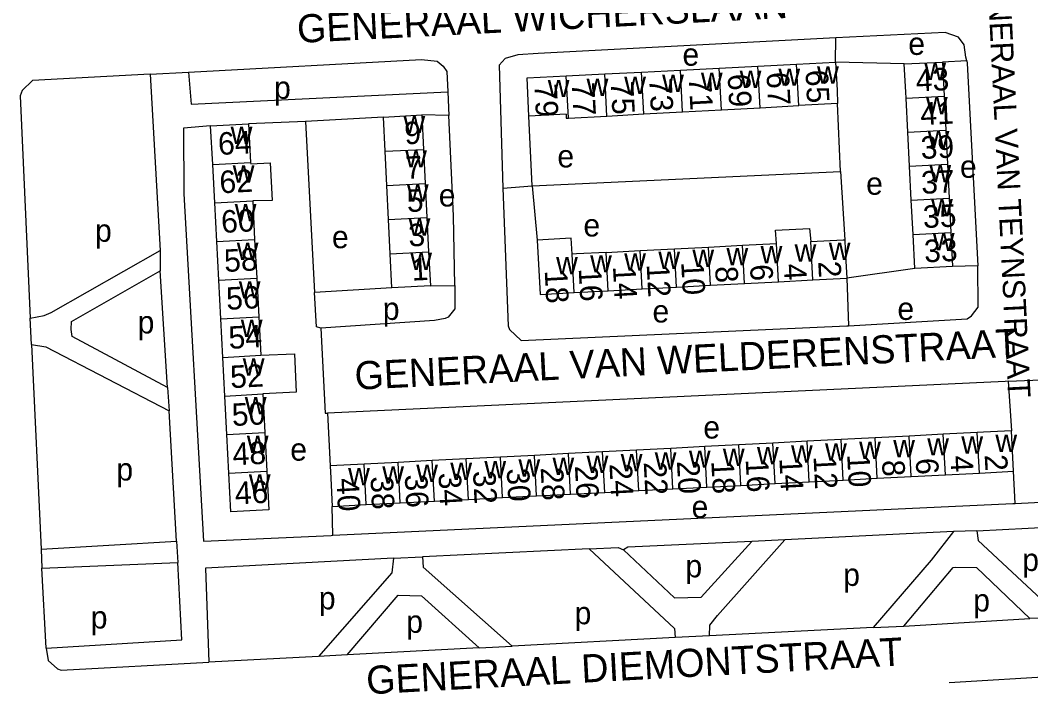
# Model space of a CAD drawing. Extents: x 159294 to 161936, y 384538 to 386517.
# Drawn here: x 161619.2 to 161798.8, y 386008.7 to 386126.3 of the extents above; entities that cross this region are included whole.
import ezdxf

# ---------------------------------------------------------------- set-up
doc = ezdxf.new("R2010")
doc.units = 0
for name, color, linetype in [('BLT_Basislijn', 7, 'Continuous'), ('BLT_Bebouwing', 7, 'Continuous'), ('BLT_Centroide', 7, 'Continuous'), ('BLT_Huisnummer', 7, 'Continuous'), ('BLT_Huisnummer_ tussenligend', 7, 'Continuous'), ('BLT_Onderverdeling_panden', 7, 'Continuous'), ('BLT_Straatnaam', 7, 'Continuous'), ('BLT_Straatnaam_verkleind', 7, 'Continuous')]:
    doc.layers.add(name, color=color, linetype=linetype)

msp = doc.modelspace()

# ---------------------------------------------------------------- linework, layer by layer
at = {"layer": 'BLT_Basislijn'}
for p, q in [((161764.11, 386118.85), (161764.14, 386123.15)), ((161776.3, 386118.52), (161764.11, 386118.85)), ((161787.4, 386119.09), (161783.1, 386118.86)), ((161642.28, 386116.7), (161649.06, 386117.08)), ((161642.28, 386116.7), (161644.03, 386085.36)), ((161695.18, 386113.54), (161695.35, 386109.36)), ((161764.98, 386099.42), (161764.46, 386111.5)), ((161695.35, 386109.36), (161690.55, 386109.45)), ((161710.18, 386096.88), (161709.6, 386109.23)), ((161669.86, 386108.29), (161659.77, 386107.88)), ((161683.73, 386109.07), (161669.86, 386108.29)), ((161669.86, 386108.29), (161671.49, 386077.92)), ((161710.18, 386096.88), (161764.98, 386099.42)), ((161764.98, 386099.42), (161765.73, 386087.27)), ((161704.95, 386096.46), (161710.18, 386096.88)), ((161710.18, 386096.88), (161711.07, 386087.22)), ((161644.03, 386085.36), (161644.06, 386081.72)), ((161778.19, 386082.17), (161766.08, 386080.46)), ((161789.36, 386082.65), (161784.88, 386082.49)), ((161645.37, 386061.03), (161644.06, 386081.72)), ((161766.08, 386080.46), (161766.42, 386071.96)), ((161685.24, 386078.71), (161671.49, 386077.92)), ((161692.07, 386079.05), (161696.45, 386079.14)), ((161621.16, 386068.63), (161620.93, 386073.33)), ((161621.16, 386068.63), (161622.88, 386032.29)), ((161645.37, 386061.03), (161645.65, 386056.83)), ((161794.75, 386062.11), (161795.35, 386053.32)), ((161646.95, 386033.66), (161645.65, 386056.83)), ((161673.77, 386056.44), (161674.24, 386047.06)), ((161796.04, 386040.41), (161795.72, 386046.11)), ((161796.04, 386040.41), (161806.44, 386040.89)), ((161674.74, 386034.73), (161674.62, 386039.86)), ((161789.19, 386035.5), (161785.08, 386035.4)), ((161789.19, 386035.5), (161806.72, 386036.45)), ((161755.06, 386033.94), (161749.19, 386033.62)), ((161785.08, 386035.4), (161755.06, 386033.94)), ((161622.88, 386032.29), (161646.95, 386033.66)), ((161622.88, 386032.29), (161623.03, 386028.88)), ((161646.95, 386033.66), (161647.17, 386029.87)), ((161720.3, 386032.31), (161690.68, 386030.9)), ((161685.51, 386030.64), (161690.68, 386030.9)), ((161623.03, 386028.88), (161647.17, 386029.87)), ((161623.81, 386014.67), (161623.03, 386028.88)), ((161776.24, 386018.59), (161798.6, 386019.96)), ((161804.16, 386020.13), (161798.6, 386019.96)), ((161770.75, 386018.32), (161741.68, 386016.84)), ((161770.75, 386018.32), (161776.24, 386018.59)), ((161735.56, 386016.56), (161706.6, 386015)), ((161741.68, 386016.84), (161735.56, 386016.56)), ((161700.77, 386014.71), (161677.29, 386013.48)), ((161700.77, 386014.71), (161706.6, 386015)), ((161672.2, 386013.2), (161652.67, 386012.16)), ((161677.29, 386013.48), (161672.2, 386013.2))]:
    msp.add_line(p, q, dxfattribs=at)
for points in [[(161787.4, 386119.09), (161787.25, 386119.71), (161786.98, 386121.9), (161785.95, 386123.26), (161783.56, 386124.1), (161764.14, 386123.15)], [(161764.14, 386123.15), (161711.23, 386120.4), (161707.6, 386120.17), (161705.35, 386119.48), (161704.28, 386118.32), (161704.95, 386096.46)], [(161649.06, 386117.08), (161690.49, 386119.3), (161693.26, 386119.01), (161694.37, 386118.15), (161695.01, 386117.19), (161695.18, 386113.54)], [(161787.4, 386119.09), (161787.5, 386118.69), (161789.36, 386082.65)], [(161642.28, 386116.7), (161621.35, 386115.6)], [(161649.06, 386117.08), (161649.53, 386111.36), (161695.18, 386113.54)], [(161621.35, 386115.6), (161619.49, 386113.8), (161619.17, 386112.83), (161620.93, 386073.33)], [(161696.45, 386079.14), (161696.19, 386091.54), (161695.35, 386109.36)], [(161653.02, 386107.53), (161648.18, 386107.13), (161648.27, 386095.46), (161651.77, 386033.68), (161674.46, 386034.72), (161674.74, 386034.73)], [(161704.95, 386096.46), (161705.93, 386071.97), (161706.16, 386071.33), (161708.21, 386069.34), (161766.11, 386071.94), (161766.42, 386071.96)], [(161620.93, 386073.33), (161623.44, 386073.79), (161624.67, 386074.34), (161644.03, 386085.36)], [(161766.42, 386071.96), (161787.46, 386073.24), (161788.26, 386073.72), (161789.44, 386075.31), (161789.36, 386082.65)], [(161645.37, 386061.03), (161628.39, 386070.06), (161628.23, 386071.31), (161628.29, 386072.76), (161644.06, 386081.72)], [(161696.45, 386079.14), (161696.44, 386074.99), (161695.25, 386073.52), (161694.7, 386073.3), (161692.82, 386072.94), (161672.6, 386071.56)], [(161672.6, 386071.56), (161671.86, 386071.81), (161671.49, 386077.92)], [(161672.6, 386071.56), (161673.37, 386056.42), (161673.77, 386056.44)], [(161621.16, 386068.63), (161623.74, 386068.21), (161645.65, 386056.83)], [(161794.75, 386062.11), (161804.96, 386062.57), (161806.44, 386040.89)], [(161794.75, 386062.11), (161794.25, 386062.09), (161673.77, 386056.44)], [(161674.74, 386034.73), (161795.62, 386040.39), (161796.04, 386040.41)], [(161789.19, 386035.5), (161789.45, 386033.78), (161804.16, 386020.13)], [(161741.68, 386016.84), (161741.77, 386018.78), (161743.11, 386020.5), (161755.06, 386033.94)], [(161785.08, 386035.4), (161781.11, 386030.31), (161770.75, 386018.32)], [(161720.3, 386032.31), (161725.47, 386032.54), (161726.4, 386032.13)], [(161720.3, 386032.31), (161735.46, 386018.15), (161735.56, 386016.56)], [(161726.4, 386032.13), (161735.47, 386023.61), (161740.23, 386023.75), (161749.19, 386033.62)], [(161749.19, 386033.62), (161727.19, 386032.62), (161726.4, 386032.13)], [(161685.51, 386030.64), (161652.11, 386028.88), (161652.67, 386012.16)], [(161685.51, 386030.64), (161685.23, 386028.08), (161672.2, 386013.2)], [(161690.68, 386030.9), (161690.77, 386029.04), (161706.6, 386015)], [(161623.81, 386014.67), (161647.88, 386016.13), (161647.17, 386029.87)], [(161776.24, 386018.59), (161784.99, 386028.98), (161785.39, 386029.06), (161789.12, 386028.98), (161798.6, 386019.96)], [(161677.29, 386013.48), (161686.35, 386024.1), (161690.49, 386023.96), (161700.77, 386014.71)], [(161623.81, 386014.67), (161624.15, 386012.48), (161625.82, 386010.98), (161626.44, 386010.74), (161652.67, 386012.16)], [(161784.28, 386008.54), (161803.88, 386009.76), (161805.74, 386009.74), (161807.33, 386008.66), (161808.62, 385995.18), (161809.8, 385968.48)]]:
    msp.add_lwpolyline(points, dxfattribs=at)
at = {"layer": 'BLT_Bebouwing'}
for p, q in [((161743.4, 386117.79), (161750.29, 386118.14)), ((161750.29, 386118.14), (161757.18, 386118.5)), ((161757.18, 386118.5), (161764.11, 386118.85)), ((161776.3, 386118.52), (161783.1, 386118.86)), ((161783.1, 386118.86), (161783.4, 386112.81)), ((161716.24, 386116.39), (161723.06, 386116.74)), ((161723.06, 386116.74), (161729.62, 386117.08)), ((161729.62, 386117.08), (161736.51, 386117.43)), ((161736.51, 386117.43), (161743.4, 386117.79)), ((161783.4, 386112.81), (161783.69, 386106.75)), ((161750.69, 386110.75), (161757.58, 386111.12)), ((161764.46, 386111.5), (161757.58, 386111.12)), ((161776.93, 386106.4), (161776.62, 386112.46)), ((161683.73, 386109.07), (161690.55, 386109.45)), ((161690.55, 386109.45), (161690.85, 386103.34)), ((161716.2, 386109.58), (161709.6, 386109.23)), ((161723.44, 386109.27), (161730.02, 386109.63)), ((161730.02, 386109.63), (161736.91, 386110)), ((161736.91, 386110), (161743.8, 386110.38)), ((161743.8, 386110.38), (161750.69, 386110.75)), ((161653.02, 386107.53), (161659.77, 386107.88)), ((161653.38, 386100.67), (161653.02, 386107.53)), ((161659.77, 386107.88), (161660.13, 386101.02)), ((161684.03, 386103), (161683.73, 386109.07)), ((161777.24, 386100.34), (161776.93, 386106.4)), ((161783.69, 386106.75), (161783.99, 386100.7)), ((161684.34, 386096.93), (161684.03, 386103)), ((161690.85, 386103.34), (161691.16, 386097.27)), ((161653.74, 386093.81), (161653.38, 386100.67)), ((161777.56, 386094.29), (161777.24, 386100.34)), ((161783.99, 386100.7), (161784.28, 386094.64)), ((161684.64, 386090.86), (161684.34, 386096.93)), ((161691.16, 386097.27), (161691.46, 386091.2)), ((161654.1, 386086.94), (161653.74, 386093.81)), ((161660.49, 386094.16), (161660.84, 386087.3)), ((161777.87, 386088.23), (161777.56, 386094.29)), ((161784.28, 386094.64), (161784.58, 386088.58)), ((161691.46, 386091.2), (161691.76, 386085.12)), ((161684.94, 386084.79), (161684.64, 386090.86)), ((161778.19, 386082.17), (161777.87, 386088.23)), ((161784.58, 386088.58), (161784.88, 386082.49)), ((161654.46, 386080.08), (161654.1, 386086.94)), ((161660.84, 386087.3), (161661.2, 386080.43)), ((161741.49, 386085.98), (161747.55, 386086.3)), ((161747.55, 386086.3), (161753.61, 386086.62)), ((161759.67, 386086.95), (161765.45, 386087.25)), ((161765.45, 386087.25), (161765.73, 386087.27)), ((161685.24, 386078.71), (161684.94, 386084.79)), ((161691.76, 386085.12), (161692.07, 386079.05)), ((161723.32, 386085.02), (161729.38, 386085.34)), ((161729.38, 386085.34), (161735.44, 386085.66)), ((161784.88, 386082.49), (161778.19, 386082.17)), ((161661.2, 386080.43), (161661.56, 386073.57)), ((161760.03, 386080.14), (161766.08, 386080.46)), ((161654.82, 386073.22), (161654.46, 386080.08)), ((161692.07, 386079.05), (161685.24, 386078.71)), ((161729.74, 386078.53), (161735.8, 386078.85)), ((161735.8, 386078.85), (161741.86, 386079.17)), ((161741.86, 386079.17), (161747.91, 386079.49)), ((161747.91, 386079.49), (161753.97, 386079.82)), ((161753.97, 386079.82), (161760.03, 386080.14)), ((161717.63, 386077.88), (161723.68, 386078.2)), ((161723.68, 386078.2), (161729.74, 386078.53)), ((161655.18, 386066.36), (161654.82, 386073.22)), ((161661.56, 386073.57), (161661.92, 386066.73)), ((161655.54, 386059.49), (161655.18, 386066.36)), ((161655.9, 386052.63), (161655.54, 386059.49)), ((161662.28, 386059.89), (161662.64, 386052.98)), ((161656.26, 386045.77), (161655.9, 386052.63)), ((161662.64, 386052.98), (161663, 386046.12)), ((161765.07, 386051.75), (161759.02, 386051.44)), ((161771.13, 386052.06), (161765.07, 386051.75)), ((161777.18, 386052.38), (161771.13, 386052.06)), ((161783.24, 386052.69), (161777.18, 386052.38)), ((161789.29, 386053), (161783.24, 386052.69)), ((161795.72, 386046.11), (161795.35, 386053.32)), ((161728.74, 386049.88), (161722.69, 386049.56)), ((161734.8, 386050.19), (161728.74, 386049.88)), ((161740.85, 386050.5), (161734.8, 386050.19)), ((161746.91, 386050.81), (161740.85, 386050.5)), ((161752.96, 386051.13), (161746.91, 386050.81)), ((161759.02, 386051.44), (161752.96, 386051.13)), ((161698.46, 386048.31), (161692.41, 386048)), ((161704.52, 386048.63), (161698.46, 386048.31)), ((161710.58, 386048.94), (161704.52, 386048.63)), ((161716.63, 386049.25), (161710.58, 386048.94)), ((161680.3, 386047.38), (161674.24, 386047.06)), ((161686.36, 386047.69), (161680.3, 386047.38)), ((161692.41, 386048), (161686.36, 386047.69)), ((161759.39, 386044.24), (161765.44, 386044.55)), ((161765.44, 386044.55), (161771.5, 386044.86)), ((161771.5, 386044.86), (161777.55, 386045.18)), ((161777.55, 386045.18), (161783.61, 386045.49)), ((161783.61, 386045.49), (161789.66, 386045.8)), ((161789.66, 386045.8), (161795.72, 386046.11)), ((161723.06, 386042.36), (161729.11, 386042.68)), ((161729.11, 386042.68), (161735.17, 386042.99)), ((161735.17, 386042.99), (161741.22, 386043.3)), ((161741.22, 386043.3), (161747.28, 386043.61)), ((161747.28, 386043.61), (161753.33, 386043.93)), ((161753.33, 386043.93), (161759.39, 386044.24)), ((161692.78, 386040.8), (161698.84, 386041.11)), ((161698.84, 386041.11), (161704.89, 386041.43)), ((161704.89, 386041.43), (161710.95, 386041.74)), ((161710.95, 386041.74), (161717, 386042.05)), ((161717, 386042.05), (161723.06, 386042.36)), ((161674.62, 386039.86), (161680.67, 386040.18)), ((161680.67, 386040.18), (161686.73, 386040.49)), ((161686.73, 386040.49), (161692.78, 386040.8))]:
    msp.add_line(p, q, dxfattribs=at)
for points in [[(161764.11, 386118.85), (161764.35, 386113.86), (161764.46, 386111.5)], [(161776.62, 386112.46), (161776.56, 386113.53), (161776.3, 386118.52)], [(161709.6, 386109.23), (161709.28, 386116.03), (161716.24, 386116.39)], [(161716.2, 386109.58), (161716.24, 386108.88), (161716.63, 386108.9)], [(161716.63, 386108.9), (161723.44, 386109.27)], [(161660.13, 386101.02), (161660.14, 386100.78), (161663.62, 386100.96), (161663.97, 386094.27), (161660.49, 386094.16)], [(161753.61, 386086.62), (161753.42, 386088.95), (161759.45, 386089.27), (161759.67, 386086.95)], [(161717.27, 386084.7), (161717.1, 386087.54), (161711.07, 386087.22)], [(161711.07, 386087.22), (161711.57, 386077.56), (161717.63, 386077.88)], [(161735.44, 386085.66), (161741.49, 386085.98)], [(161765.73, 386087.27), (161765.83, 386085.46), (161766.08, 386080.46)], [(161723.32, 386085.02), (161718.03, 386084.74), (161717.27, 386084.7)], [(161661.92, 386066.73), (161667.92, 386066.98), (161668.2, 386060.17), (161662.28, 386059.89)], [(161795.35, 386053.32), (161790.36, 386053.06), (161789.29, 386053)], [(161722.69, 386049.56), (161716.63, 386049.25)], [(161674.24, 386047.06), (161674.36, 386044.86), (161674.62, 386039.86)], [(161663, 386046.12), (161663.36, 386039.26), (161656.62, 386038.9), (161656.26, 386045.77)]]:
    msp.add_lwpolyline(points, dxfattribs=at)
at = {"layer": 'BLT_Onderverdeling_panden'}
for p, q in [((161750.69, 386110.75), (161750.29, 386118.14)), ((161757.58, 386111.12), (161757.18, 386118.5)), ((161716.63, 386108.9), (161716.24, 386116.39)), ((161723.44, 386109.27), (161723.06, 386116.74)), ((161730.02, 386109.63), (161729.62, 386117.08)), ((161736.91, 386110), (161736.51, 386117.43)), ((161743.8, 386110.38), (161743.4, 386117.79)), ((161776.62, 386112.46), (161783.4, 386112.81)), ((161776.93, 386106.4), (161783.69, 386106.75)), ((161684.03, 386103), (161690.85, 386103.34)), ((161653.38, 386100.67), (161660.13, 386101.02)), ((161777.24, 386100.34), (161783.99, 386100.7)), ((161684.34, 386096.93), (161691.16, 386097.27)), ((161653.74, 386093.81), (161660.49, 386094.16)), ((161777.56, 386094.29), (161784.28, 386094.64)), ((161684.64, 386090.86), (161691.46, 386091.2)), ((161777.87, 386088.23), (161784.58, 386088.58)), ((161654.1, 386086.94), (161660.84, 386087.3)), ((161741.86, 386079.17), (161741.49, 386085.98)), ((161747.91, 386079.49), (161747.55, 386086.3)), ((161753.97, 386079.82), (161753.61, 386086.62)), ((161760.03, 386080.14), (161759.67, 386086.95)), ((161684.94, 386084.79), (161691.76, 386085.12)), ((161717.63, 386077.88), (161717.27, 386084.7)), ((161723.68, 386078.2), (161723.32, 386085.02)), ((161729.74, 386078.53), (161729.38, 386085.34)), ((161735.8, 386078.85), (161735.44, 386085.66)), ((161654.46, 386080.08), (161661.2, 386080.43)), ((161654.82, 386073.22), (161661.56, 386073.57)), ((161655.18, 386066.36), (161661.92, 386066.73)), ((161655.54, 386059.49), (161662.28, 386059.89)), ((161655.9, 386052.63), (161662.64, 386052.98)), ((161765.44, 386044.55), (161765.07, 386051.75)), ((161771.5, 386044.86), (161771.13, 386052.06)), ((161777.55, 386045.18), (161777.18, 386052.38)), ((161783.61, 386045.49), (161783.24, 386052.69)), ((161789.66, 386045.8), (161789.29, 386053)), ((161729.11, 386042.68), (161728.74, 386049.88)), ((161735.17, 386042.99), (161734.8, 386050.19)), ((161741.22, 386043.3), (161740.85, 386050.5)), ((161747.28, 386043.61), (161746.91, 386050.81)), ((161753.33, 386043.93), (161752.96, 386051.13)), ((161759.39, 386044.24), (161759.02, 386051.44)), ((161698.84, 386041.11), (161698.46, 386048.31)), ((161704.89, 386041.43), (161704.52, 386048.63)), ((161710.95, 386041.74), (161710.58, 386048.94)), ((161717, 386042.05), (161716.63, 386049.25)), ((161723.06, 386042.36), (161722.69, 386049.56)), ((161680.67, 386040.18), (161680.3, 386047.38)), ((161686.73, 386040.49), (161686.36, 386047.69)), ((161692.78, 386040.8), (161692.41, 386048)), ((161656.26, 386045.77), (161663, 386046.12))]:
    msp.add_line(p, q, dxfattribs=at)

# ---------------------------------------------------------------- texts
at = {"layer": 'BLT_Centroide'}
for s, p in [('e', (161777.02, 386120.13)), ('e', (161736.88, 386118.21)), ('w', (161779.86, 386115.66)), ('w', (161733.27, 386113.53)), ('w', (161740.16, 386113.91)), ('w', (161747.05, 386114.27)), ('w', (161753.94, 386114.64)), ('w', (161760.81, 386115)), ('p', (161664.29, 386112.32)), ('w', (161712.94, 386112.62)), ('w', (161719.84, 386112.81)), ('w', (161726.53, 386113.17)), ('w', (161780.16, 386109.59)), ('w', (161687.29, 386106.22)), ('w', (161656.58, 386104.28)), ('w', (161780.46, 386103.56)), ('w', (161687.59, 386100.12)), ('e', (161714.65, 386100.13)), ('w', (161656.94, 386097.41)), ('w', (161780.77, 386097.5)), ('e', (161786.21, 386098.28)), ('e', (161769.53, 386095.27)), ('w', (161687.9, 386094.06)), ('e', (161693.57, 386093.18)), ('w', (161657.3, 386090.56)), ('w', (161781.07, 386091.44)), ('p', (161632.47, 386086.92)), ('w', (161688.2, 386088)), ('e', (161719.28, 386087.85)), ('e', (161674.58, 386085.77)), ('w', (161781.38, 386085.38)), ('w', (161657.66, 386083.69)), ('w', (161744.7, 386082.73)), ('w', (161750.77, 386083.06)), ('w', (161756.81, 386083.38)), ('w', (161762.88, 386083.7)), ('w', (161688.5, 386081.91)), ('w', (161714.42, 386081.14)), ('w', (161720.47, 386081.45)), ('w', (161726.53, 386081.77)), ('w', (161732.59, 386082.09)), ('w', (161738.64, 386082.42)), ('w', (161658.02, 386076.83)), ('p', (161683.62, 386073.02)), ('e', (161731.55, 386072.56)), ('e', (161775.09, 386073.02)), ('p', (161640.04, 386070.62)), ('w', (161658.38, 386069.97)), ('w', (161658.73, 386063.09)), ('w', (161659.09, 386056.23)), ('e', (161740.59, 386051.93)), ('w', (161659.45, 386049.38)), ('w', (161774.34, 386048.61)), ('w', (161780.39, 386048.92)), ('w', (161786.45, 386049.23)), ('w', (161792.5, 386049.55)), ('e', (161667.17, 386048)), ('w', (161744.06, 386047.05)), ('w', (161750.12, 386047.36)), ('w', (161756.17, 386047.67)), ('w', (161762.23, 386047.98)), ('w', (161768.28, 386048.3)), ('w', (161707.73, 386045.17)), ('w', (161713.78, 386045.48)), ('w', (161719.84, 386045.8)), ('w', (161725.91, 386046.11)), ('w', (161731.95, 386046.42)), ('w', (161738.02, 386046.73)), ('p', (161636.26, 386044.47)), ('w', (161677.45, 386043.61)), ('w', (161683.52, 386043.92)), ('w', (161689.56, 386044.23)), ('w', (161695.62, 386044.55)), ('w', (161701.67, 386044.86)), ('w', (161659.81, 386042.5)), ('e', (161738.5, 386037.8)), ('p', (161737.41, 386027.26)), ('p', (161797.27, 386028.39)), ('p', (161765.45, 386025.74)), ('p', (161672.25, 386021.57)), ('p', (161788.56, 386021.19)), ('p', (161631.71, 386018.16)), ('p', (161717.71, 386018.92)), ('p', (161687.78, 386017.4))]:
    msp.add_text(s, height=4, dxfattribs=at).set_placement(p)
at = {"layer": 'BLT_Huisnummer'}
for s, rotation, p in [('69', 273.1062, (161744.9, 386116.68)), ('65', 273.1062, (161758.73, 386117.4)), ('43', 2.7389, (161778.43, 386113.61)), ('79', 273.1062, (161710.54, 386114.91)), ('73', 273.1062, (161730.96, 386115.89)), ('9', 2.7862, (161687.54, 386104.22)), ('64', 3.0471, (161654.43, 386102.33)), ('37', 2.7389, (161779.4, 386095.42)), ('5', 2.7862, (161687.96, 386092.18)), ('58', 3.0471, (161655.51, 386081.53)), ('33', 2.7389, (161779.92, 386083.24)), ('1', 2.7862, (161688.81, 386079.99)), ('14', 273.053, (161724.52, 386082.51)), ('10', 273.053, (161736.65, 386083.28)), ('6', 273.053, (161748.88, 386082.82)), ('2', 273.053, (161761, 386083.39)), ('18', 273.053, (161712.39, 386081.79)), ('54', 3.0471, (161656.3, 386067.86)), ('50', 3.0471, (161656.88, 386054.15)), ('14', 272.9534, (161754.1, 386048.42)), ('10', 272.9534, (161766.15, 386049.1)), ('6', 272.9534, (161778.33, 386048.38)), ('2', 272.9534, (161790.59, 386049.02)), ('30', 272.9534, (161705.63, 386046.56)), ('26', 272.9534, (161717.76, 386047.07)), ('22', 272.9534, (161729.99, 386047.71)), ('18', 272.9534, (161742, 386047.93)), ('46', 3.0471, (161657.42, 386040.21)), ('40', 272.9534, (161675.36, 386044.82)), ('34', 272.9534, (161693.5, 386045.8))]:
    msp.add_text(s, height=4, rotation=rotation, dxfattribs=at).set_placement(p)
at = {"layer": 'BLT_Huisnummer_ tussenligend'}
for s, rotation, p in [('67', 273.1062, (161751.8, 386117)), ('77', 273.1062, (161717.2, 386115.17)), ('75', 273.1062, (161724.13, 386115.36)), ('71', 273.1062, (161737.99, 386116.12)), ('41', 2.7389, (161779.24, 386107.64)), ('39', 2.7389, (161779.31, 386101.62)), ('7', 2.7862, (161687.74, 386098.07)), ('62', 3.0471, (161654.68, 386095.51)), ('35', 2.7389, (161779.71, 386089.34)), ('60', 3.0471, (161654.98, 386088.47)), ('3', 2.7862, (161688.25, 386086.06)), ('12', 273.053, (161730.51, 386082.9)), ('8', 273.053, (161742.68, 386082.49)), ('4', 273.053, (161754.86, 386082.93)), ('16', 273.053, (161718.43, 386082.14)), ('56', 3.0471, (161655.88, 386074.8)), ('52', 3.0471, (161656.58, 386060.88)), ('48', 3.0471, (161657.01, 386047.15)), ('12', 272.9534, (161760.17, 386048.77)), ('4', 272.9534, (161784.5, 386048.83)), ('28', 272.9534, (161711.67, 386046.75)), ('24', 272.9534, (161723.9, 386047.41)), ('20', 272.9534, (161735.89, 386047.92)), ('16', 272.9534, (161748.11, 386048.21)), ('8', 272.9534, (161772.34, 386048.05)), ('38', 272.9534, (161681.42, 386045.16)), ('36', 272.9534, (161687.51, 386045.48)), ('32', 272.9534, (161699.64, 386046.13))]:
    msp.add_text(s, height=4, rotation=rotation, dxfattribs=at).set_placement(p)
at = {"layer": 'BLT_Straatnaam'}
for s, height, rotation, p in [('GENERAAL WICHERSLAAN', 4.9999, 2.9263, (161668.5, 386122.25)), ('GENERAAL VAN WELDERENSTRAAT', 5, 2.8712, (161678.73, 386060.59)), ('GENERAAL DIEMONTSTRAAT', 5, 3.0969, (161680.81, 386006.45))]:
    msp.add_text(s, height=height, rotation=rotation, dxfattribs=at).set_placement(p)
at = {"layer": 'BLT_Straatnaam_verkleind'}
msp.add_text('GENERAAL VAN TEYNSTRAAT', height=3.9999, rotation=272.8423, dxfattribs=at).set_placement((161790.89, 386137.51))

doc.saveas('drawing.dxf')
